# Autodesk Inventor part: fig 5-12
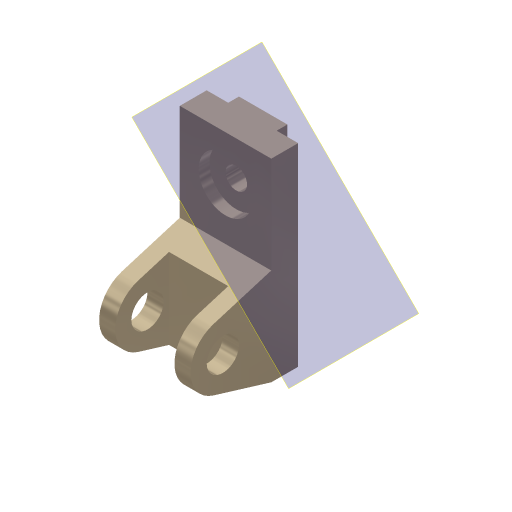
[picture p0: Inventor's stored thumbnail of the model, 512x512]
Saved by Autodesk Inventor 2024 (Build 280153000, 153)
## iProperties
Shininess: 65.0
Angle Display Precision: 2
Document Length Units: 11269
Document Angle Units: 11279
Document Time Units: 11290
Document Mass Units: 11283
Document Length Units Precision: 3
Document Angle Units Precision: 2
Compacted: False
Created: 2001-11
Part Number: fig 5-12
Document SubType Name: Modeling
Designer: Renu Muthoo
Density: 1 g/cm^3
Material: Generic
Appearance: Metal-Titanium (Polished)
Density: 0.0
Volumn: 0.0
Area: 0.0
PropertySet Name: Model Information
Control State: 0
Master: False
Checked Out: False
Author: Renu Muthoo
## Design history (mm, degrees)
sketch "Sketch2"
  geometry: L1 (33.257, 104.664)-(33.257, -75.336); L2 (33.257, -75.336)-(8.257, -75.336); L3 (8.257, -75.336)-(-45.451, -59.045); L4 (-45.451, -1.628)-(8.257, 14.664); L5 (8.257, 14.664)-(8.257, 104.664); L6 (8.257, 104.664)-(33.257, 104.664); C1 r 15 at (-36.743, -30.336); A1 r 30 centre (-36.743, -30.336) between (-45.451, -1.628) and (-45.451, -59.045)
  constraints: 12 end point, 2 centre point, 2 equal length, 2 parallel, 2 point on circle, 2 tangent, 1 coincident, 1 perpendicular, 1 vertical
  dimensions: "d0" = 180 distance of L1.start L1.end; "d1" = 30 radius of A1; "d2" = 25 distance of L5.end L1.start; "d3" = 45 distance from line of L2 A1.centre; "d4" = 70 distance from line of L1 A1.centre; "d5" = 30 diameter of C1
extrude "Extrusion1" new body sketch "Sketch2" distance "d6" = 85; taper "d7" = 0 deg
workplane "Work Plane1"
sketch "Sketch3"
  geometry: L1 (15, 62.364)-(70, 62.364); L2 (70, 62.364)-(70, -52.386); L3 (70, -52.386)-(15, -52.386); L4 (15, -52.386)-(15, 62.364); L5 (0, -45)-(0, -28.708) reference
  constraints: 8 end point, 2 parallel, 1 horizontal, 1 perpendicular
  dimensions: "d8" = 55 distance of L1.start L1.end; "d9" = 15 distance between parallel lines of L5 L4
extrude "Extrusion2" cut sketch "Sketch3" distance "d10" = 50; taper "d11" = 0 deg
sketch "Sketch4"
  geometry: L1 (0, 25)-(85, 25) reference; L2 (0, 0)-(0, 25) reference; L3 (20, 25)-(65, 25); L4 (65, 25)-(65, 35); L5 (65, 35)-(20, 35); L6 (20, 35)-(20, 25)
  constraints: 8 end point, 2 parallel, 1 horizontal, 1 perpendicular, 1 point on line
  dimensions: "d12" = 45 distance of L4.end L5.end; "d13" = 10 distance of L3.end L4.end; "d14" = 20 distance between parallel lines of L2 L6
extrude "Extrusion3" join sketch "Sketch4" stored distance "d15" = 50; taper "d16" = 0 deg
sketch "Sketch5"
  geometry: L1 (85, 0)-(85, 90) reference; L2 (0, 90)-(85, 90) reference; 1 further point
  dimensions: "d17" = 42 distance from line of L2 point (42.5, 48); "d18" = 42.5 distance from line of L1 point (42.5, 48)
hole "Hole1" sketch "Sketch5" diameter "d19" = 20; stored, may be unused: countersink angle "d23" = 82 deg, drill point angle "d25" = 118 deg; dims "d20" = 6, "d21" = 50, "d22" = 10, "d24" = 8
workplane "Work Plane8"
body "Solid1"
node "Sketch1"
other parameters: "d28" = 135 deg
